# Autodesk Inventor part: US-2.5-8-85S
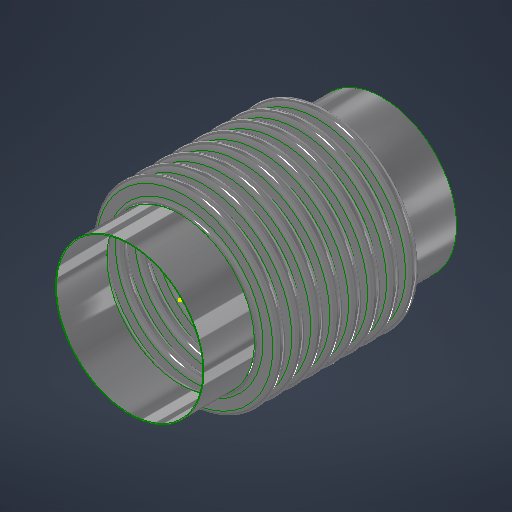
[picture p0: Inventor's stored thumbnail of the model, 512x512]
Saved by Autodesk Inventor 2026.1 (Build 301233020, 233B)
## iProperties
Category: 26 GA (0.018 THICK)
RuleStatus: InUse
Created: 2026-07
Part Number: US-2.5-8-85S
Project: =STOCK BELLOWS: <Stock Number><SFILL>
Material: ASTM A240-304
Description: =STOCK BELLOWS: <Stock Number>, <SID_> I.D., <SOD_> O.D., <SPLY_> PLY, <Category>, <SNET_CONS> CONS.<PITCH_><STANGENT_> TANGENT<SFILL>
Document SubType Name: Sheet Metal
Designer: LC
Stock Number: U.S-2.5-8-85S
Surface Area: 659.127 cm^2
Volume: 56.61 cm^3
Sheet Metal Rule: Default
Appearance: STAINLESS STEEL
NET_TUBE: 3.428
COUNTER: 1.500
PBAR: 1.214
PSET: 5.356
PLY: 2
CONS: 2
THK: 0.036
ID: 4.500
OD: 5.500
CONS_: 2
TANGENT: 0.500
PITCH: 0.375
BELLOWS_UPSET: 0.000
NET_CONS: 2
S_CONS: 0
Description_Units: 0
ID_M: 114.30 mm
OD_M: 139.70 mm
THK_M: 0.91 mm
ID_U: 4.500 in
OD_U: 5.500 in
THK_U: 0.036 in
TANGENT2: 0.500
d79: 1.000
d82: 1.000
d83: 26.000
d84: 24.000
d80: 2.571
d81: 10
SID: 2.375
SCONS_: 8
SPITCH: 0.250
SBELLOWS_UPSET: 0.000
SNET_CONS: 8
SS_CONS: 0
SCONS: 8
d174: 8
d177: 0.018
d178: 2.375
d179: 3.000
d180: 0.375
d181: 1.000
d182: 0.000
d190: 8
d191: 1
d192: 1
d193: 8
d194: 0
PART_NUMBER: U.S-2.5-8-85S
PRESSURE: 85
SIZE: 2.50
STANGENT_: 1.000
d214: 8
d217: 0.030
d218: 6.625
d219: 8.125
d220: 0.500
d221: 1.000
d222: 0.000
d230: 8
d231: 1
d232: 1
d233: 8
d234: 0
STANGENT: 4.000
SPLY_: 1
STHK_: 0.018
SID_: 2.900
SOD_: 3.700
SPITCH_: 0.375
STANGENT__: 1.000
SBELLOWS_UPSET_: 0.000
SDIFF_TAN: 1.000
TAN_TO_TAN: 0.750 in
d252: 2
d275: 2
d287: 0.050
d289: 0.500
d290: 0.000
d263: 2
d265: 1
d268: 2
d269: 0
d286: 2
d288: 1
d291: 2
d292: 0
SOD_NECK: 2 15/16
CFILL: .
SFILL: .
PITCH_: =, <SPITCH_> PITCH,
SREROLL: 0.750
MATTABLE: 20 GA (0.036 THICK)
MESH: ,
CSECT: 2
Author: LC
Keywords: 20 GA (0.036 THICK)
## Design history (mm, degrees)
sketch "Sketch2"
  geometry: L1 (0, -183.595)-(0, 600.956) reference; L2 (58.979, 0)-(57.15, 0); L3 (60.446, -1.467)-(66.554, -1.467); L4 (60.446, -3.296)-(66.554, -3.296); L5 (66.554, -8.058)-(60.446, -8.058); L6 (66.554, -6.229)-(60.446, -6.229); L7 (58.979, -9.525)-(57.15, -9.525); L8 (60.446, 0)-(60.446, -9.525); L9 (66.554, -4.762)-(69.85, -4.763); L10 (57.15, 0)-(57.15, -9.525); L11 (20.376, 102.841)-(20.376, 101.926); L12 (58.262, 488.877)-(58.262, 349.177); L13 (58.262, 479.352)-(58.262, 339.652); L14 (93.133, -58.817)-(93.133, -71.517); L15 (118.746, -66.401)-(118.746, -66.401); L16 (66.554, -6.229)-(66.554, -8.058); L17 (60.446, -6.229)-(60.446, -8.058); L18 (60.446, -7.144)-(66.554, -7.144); L19 (69.85, 0)-(69.85, -9.525); L20 (-66.554, -6.229)-(-66.554, -8.058); L21 (-66.554, -1.467)-(-60.446, -1.467); L22 (-66.554, -3.296)-(-60.446, -3.296); L23 (-60.446, -6.229)-(-66.554, -6.229); L24 (-66.554, -7.144)-(-60.446, -7.144); L25 (-60.446, -8.058)-(-66.554, -8.058); L26 (-60.446, -6.229)-(-60.446, -8.058); L27 (-57.15, -2.522)-(-57.15, -12.047); L28 (-60.446, -4.763)-(-57.15, -4.763); L29 (-66.554, 3.828)-(-66.554, -9.525); L30 (-68.021, 0)-(-69.85, 0); L31 (-69.85, 0)-(-69.85, -9.525); L32 (-68.021, -9.525)-(-69.85, -9.525); A1 r 1.467 centre (60.446, 0) between (58.979, 0) and (60.446, -1.467); A2 r 3.296 centre (60.446, 0) between (57.15, 0) and (60.446, -3.296); A3 r 3.296 centre (66.554, -4.762) between (66.554, -8.058) and (66.554, -1.467); A4 r 1.467 centre (66.554, -4.762) between (66.554, -6.229) and (66.554, -3.296); A5 r 1.467 centre (60.446, -9.525) between (60.446, -8.058) and (58.979, -9.525); A6 r 3.296 centre (60.446, -9.525) between (60.446, -6.229) and (57.15, -9.525); A7 r 2.381 centre (66.554, -4.762) between (66.554, -7.144) and (68.936, -4.762); A8 r 2.381 centre (60.446, -9.525) between (60.446, -7.144) and (58.064, -9.525); A9 r 1.467 centre (-66.554, -9.525) between (-66.554, -8.058) and (-68.021, -9.525); A10 r 1.467 centre (-60.446, -4.763) between (-60.446, -6.229) and (-60.446, -3.296); A11 r 2.381 centre (-60.446, -4.763) between (-60.446, -7.144) and (-58.064, -4.763); A12 r 3.296 centre (-60.446, -4.763) between (-60.446, -8.058) and (-60.446, -1.467); A13 r 2.381 centre (-66.554, -9.525) between (-66.554, -7.144) and (-68.936, -9.525); A14 r 3.296 centre (-66.554, -9.525) between (-66.554, -6.229) and (-69.85, -9.525); A15 r 1.467 centre (-66.554, 0) between (-68.021, 0) and (-66.554, -1.467); A16 r 3.296 centre (-66.554, 0) between (-69.85, 0) and (-66.554, -3.296); 10 further points
  constraints: 62 end point, 38 point on circle, 20 tangent, 16 centre point, 12 parallel, 9 midpoint, 7 vertical, 6 coincident, 6 concentric, 6 point on line, 4 equal radius, 4 perpendicular, 3 horizontal, 1 collinear, 1 horizontal alignment, 10 other
  dimensions: "THK" = 0.9144 distance of L11.start L11.end; "ID" = 114.3 distance of L11.end point (20.376, -12.374); "OD" = 139.7 distance of L12.start L12.end; "PITCH" = 9.525 distance of L12.start L13.start; "TANGENT" = 12.7 distance of L14.start L14.end; "BELLOWS_UPSET" = 0 distance of L15.start L15.end; "d43" = 114.3 diameter of L10 L1 (= ID); "d44" = 139.7 diameter of L9.end L1 (= OD); "d45" = 1.8288 distance between parallel lines of L5 L6 (computed from THK, PLY); "d46" = 3.29565 radius of A3 (computed from PITCH, THK, PLY); "UPSET_PITCH" = 9.525 distance of L2.end L7.end (derived); "SIDEWALL_ANGLE" = 0 deg angle of L3 L9 (derived); "CON_GAP" = 2.9337 distance of point (60.446, -6.229) point (60.446, -3.296) (derived); "TAN1" = 3.74046 dimension on A8 (derived); "TAN2" = 3.74046 dimension on A7 (derived); "LEG1" = 6.1087 distance of L18.start L18.end (derived); "d278" = 1.8288 distance between parallel lines of L25 L23 (derived); "d279" = 3.29565 radius of A12 (derived); "d280" = 9.525 distance of L30.end L31.end (derived); "d281" = 360 deg dimension on L21 L28 (derived); "d282" = 2.9337 distance of point (-66.554, -6.229) point (-66.554, -3.296) (derived); "d283" = 3.74046 dimension on A13 (derived); "d284" = 3.74046 dimension on A11 (derived); "d285" = 6.1087 distance of L24.start L24.end (derived); "d293" = 114.3 diameter of L27 L1 (derived); "d294" = 139.7 diameter of L31 L1 (derived)
  node "Sketch Rectangular Pattern1" dims "d31" = 25.4, "ID" = 114.3
  node "Sketch Rectangular Pattern2" dims "d39" = 25.4, "PITCH" = 9.525
revolve "CONS" stored, may be unused: angle "d48" = 90 deg
node "BELLOW MIDPLANE"
pattern_linear "Rectangular Pattern2" dims "d52" = 9.525 (= UPSET_PITCH)
sketch "Sketch5"
  geometry: C1 r 58.979 at (0, 0) reference; C2 r 57.15 at (0, 0) reference
extrude "TANGENT" new body sketch "Sketch5" distance "d53" = 12.7 (= TANGENT); taper "d54" = 0 deg
revolve "SAMETAN" stored, may be unused: angle "d65" = 90 deg
revolve "DIFFTAN" stored, may be unused: angle "d70" = 90 deg
sketch "Sketch9"
  geometry: L1 (58.391, 0)-(-58.391, 0) reference; L2 (0, -17.78)-(0, 17.78) reference; L3 (41.708, 0)-(-41.708, 0); L4 (41.708, -11.906)-(41.708, 11.906); L5 (29.008, -11.906)-(29.008, 11.906); L6 (15.418, 11.906)-(15.418, -11.906); L7 (-29.008, -11.906)-(-29.008, 11.906); L8 (-41.708, -11.906)-(-41.708, 11.906); L9 (40.914, -11.906)-(40.914, 11.906); L10 (41.708, -11.906)-(40.914, -11.906); L11 (41.708, 11.906)-(40.914, 11.906); L12 (15.815, 11.906)-(15.022, 11.906); L13 (15.022, 11.906)-(15.022, -11.906); L14 (15.022, -11.906)-(15.815, -11.906); L15 (15.815, -11.906)-(15.815, 11.906); L16 (-15.815, 11.906)-(-15.815, -11.906); L17 (-15.418, 11.906)-(-15.418, -11.906); L18 (-15.815, -11.906)-(-15.022, -11.906); L19 (-15.022, -11.906)-(-15.022, 11.906); L20 (-15.022, 11.906)-(-15.815, 11.906); L21 (-41.708, -11.906)-(-40.914, -11.906); L22 (-40.914, -11.906)-(-40.914, 11.906); L23 (-40.914, 11.906)-(-41.708, 11.906); L24 (-41.708, 11.906)-(-41.708, -11.906); L25 (41.708, -0.397)-(-41.708, -0.397); L26 (-41.708, -0.397)-(-41.708, 0.397); L27 (-41.708, 0.397)-(41.708, 0.397); L28 (41.708, 0.397)-(41.708, -0.397); L29 (-41.708, 11.906)-(41.708, 11.906); L30 (41.708, 11.906)-(41.708, 12.7); L31 (41.708, 12.7)-(-41.708, 12.7); L32 (-41.708, 12.7)-(-41.708, 11.906); L33 (41.708, -11.906)-(-41.708, -11.906); L34 (-41.708, -11.906)-(-41.708, -12.7); L35 (-41.708, -12.7)-(41.708, -12.7); L36 (41.708, -12.7)-(41.708, -11.906); 30 further points
  constraints: 68 end point, 13 midpoint, 13 parallel, 8 horizontal, 7 perpendicular, 6 equal length, 3 point on line, 2 vertical, 14 other
  dimensions: "d115" = 23.8125 distance of L4.start L4.end (derived); "d116" = 12.7 distance between parallel lines of L4 L5 (derived); "d117" = 13.58962 distance between parallel lines of L5 L6 (derived); "d125" = 44.42645 distance between parallel lines of L7 L6 (derived); "d127" = 12.7 distance between parallel lines of L8 L7 (derived); "d128" = 26.28962 distance between parallel lines of L6 L4 (derived); "d130" = 83.41607 distance between parallel lines of L8 L4 (derived); "RULER_THK" = 0.79375 distance between parallel lines of L4 L9; "d135" = 0.79375 distance of L13.end L14.end (derived); "d138" = 30.83684 distance of L13.end L16.end (derived); "d143" = 0.79375 distance of L22.end L8.end (derived); "d144" = 0.79375 distance between parallel lines of L27 L25 (derived)
extrude "RULER" join sketch "Sketch9" distance "d149" = 0.79375 (derived); taper "d150" = 0 deg
extrude "BARS" join sketch "Sketch9" distance "d151" = 0.79375 (derived); taper "d152" = 0 deg
pattern_linear "Rectangular Pattern4" dims "d155" = 30.83684 (derived)
sketch "Sketch13"
  geometry: L1 (93.149, -52.467)-(93.149, -77.867); L2 (37.287, 0)-(36.83, 0); L3 (37.287, -9.525)-(36.83, -9.525); L4 (44.38, -7.372)-(39.44, -7.372); L5 (44.38, -6.915)-(39.44, -6.915); L6 (44.38, -4.762)-(46.99, -4.762); L7 (39.44, -2.153)-(44.38, -2.153); L8 (39.44, 0)-(39.44, -9.525); L9 (36.83, 0)-(36.83, -9.525); L10 (58.254, -367.738)-(58.254, -461.718); L11 (58.254, -377.263)-(58.254, -471.243); L12 (58.254, -396.313)-(58.254, -490.293); L13 (58.254, -405.838)-(58.254, -499.818); L14 (58.254, -415.363)-(58.254, -509.343); L15 (58.254, -424.888)-(58.254, -518.868); L16 (58.254, -434.413)-(58.254, -528.393); L17 (58.254, -386.788)-(58.254, -480.768); L18 (20.376, 102.383)-(20.376, 101.926); L19 (39.44, -2.61)-(44.38, -2.61); L20 (0, -640.324)-(0, 226.168) reference; L21 (-23.752, 0)-(142.514, 0) reference; A1 r 2.153 centre (39.44, 0) between (37.287, 0) and (39.44, -2.153); A2 r 2.153 centre (39.44, -9.525) between (39.44, -7.372) and (37.287, -9.525); A3 r 2.61 centre (39.44, -9.525) between (39.44, -6.915) and (36.83, -9.525); A4 r 2.153 centre (44.38, -4.762) between (44.38, -6.915) and (44.38, -2.61); A5 r 2.61 centre (44.38, -4.762) between (44.38, -7.372) and (44.38, -2.153); A6 r 2.61 centre (39.44, 0) between (36.83, 0) and (39.44, -2.61); 6 further points; 1 other entity
  constraints: 38 end point, 15 point on circle, 9 tangent, 6 centre point, 6 parallel, 5 vertical alignment, 4 point on line, 4 vertical, 3 coincident, 3 concentric, 2 collinear, 2 equal radius, 1 horizontal, 1 perpendicular, 23 other
  dimensions: "SBELLOWS_UPSET_" = 0 distance of point (118.762, -66.401) point (118.762, -66.401); "STOTAL_THK_BELLOW__" = 0.4572 distance between parallel lines of L4 L5 (derived); "d224" = 2.60985 radius of A5 (derived); "d225" = 9.525 distance of L2.end L3.end (derived); "SSIDEWALL_ANGLE_" = 0 deg angle of L7 L6 (derived); "SSCON_GAP_" = 4.3053 distance of point (39.44, -6.915) point (39.44, -2.61) (derived); "d235" = 73.66 diameter of L9 L20 (derived); "d236" = 93.98 diameter of L6.end L20 (derived)
  node "Sketch Rectangular Pattern4" dims "d228" = 25.4
  node "Sketch Rectangular Pattern5" dims "d229" = 25.4
revolve "SBELLOW" stored, may be unused: angle "d197" = 90 deg
pattern_linear "Rectangular Pattern5" dims "d204" = 9.525 (derived)
revolve "STANGENT" stored, may be unused: angle "d240" = 90 deg
revolve "SSAMETAN" stored, may be unused: angle "d241" = 90 deg
revolve "SDIFFTAN" stored, may be unused: angle "d246" = 90 deg
revolve "INVCON" stored, may be unused: angle "d295" = 90 deg
pattern_linear "Rectangular Pattern6" dims "d298" = 9.525 (derived)
revolve "INVTANGENT" stored, may be unused: angle "d302" = 90 deg
revolve "INVSAMETAN" stored, may be unused: angle "d307" = 90 deg
revolve "INVDIFFTAN" stored, may be unused: angle "d312" = 90 deg
sketch "ID BELLOW MOUNT CALC"
  geometry: L1 (44.45, 0)-(38.1, 0); L2 (38.1, 0)-(38.1, 12.7); L3 (38.1, 12.7)-(44.45, 12.7); L4 (44.45, 12.7)-(44.45, 0); L5 (36.513, 12.7)-(34.684, 12.7); L6 (34.684, 12.7)-(34.684, 0); L7 (34.684, 0)-(36.513, 0); L8 (36.513, 0)-(36.513, 12.7); L9 (0, -2.54)-(0, 15.24) reference; L10 (-8.89, 0)-(53.34, 0) reference; 1 further point
  constraints: 16 end point, 5 parallel, 2 collinear, 2 horizontal, 2 perpendicular
  dimensions: "d314" = 12.7 distance of L5.end L6.end (derived); "d315" = 1.8288 distance of L5.start L5.end (derived); "IG" = 1.5875 distance between parallel lines of L2 L8; "PIPE_OD" = 88.9 diameter of L4 L9; "PIPE_WALL" = 6.35 distance of L2.end L3.end; "ID_MT_BELLOW" = 69.3674 diameter of L6 L9 (derived)
revolve "CFILL" stored, may be unused: angle "d320" = 90 deg
pattern_linear "Rectangular Pattern7" dims "d323" = 9.525 (derived)
revolve "SFILL" stored, may be unused: angle "d324" = 90 deg
pattern_linear "Rectangular Pattern8" dims "d327" = 9.525 (derived)
node "STOCK BELLOW MIDPLANE"
sketch "Sketch21"
  geometry: L1 (0, -100.013)-(0, 100.013) reference; L2 (-100.013, 0)-(100.013, 0) reference; L3 (-0.099, 71.437)-(0.099, 71.437); L4 (0.099, 71.437)-(0.099, 55.562); L5 (0.099, 55.562)-(-0.099, 55.562); L6 (-0.099, 55.562)-(-0.099, 71.437); C1 r 55.562 at (0, 0); C2 r 71.437 at (0, 0); 3 further points
  constraints: 8 end point, 2 centre point, 2 coincident, 2 parallel, 2 tangent, 1 horizontal, 1 perpendicular, 1 other
  dimensions: "d329" = 111.125 diameter of C1 (derived); "d330" = 142.875 diameter of C2 (derived); "d331" = 0.19844 distance of L3.start L3.end
extrude "CLAMSHELL" cut sketch "Sketch21" extent not by distance; stored distance "d332" = 0; taper "d333" = 0 deg
pattern_circular "Circular Pattern1" dims angle "d335" = 180 deg (derived)
node "BELLOW"
sketch "Sketch6"
  geometry: L1 (-19.05, 58.979)-(-6.35, 58.979); L2 (-6.35, 58.979)-(-6.35, 57.15); L3 (-6.35, 57.15)-(-19.05, 57.15); L4 (-19.05, 57.15)-(-19.05, 58.979); L5 (2.54, 0)-(-59.69, 0) reference; L6 (-38.1, -108.388)-(-38.1, 156.601) reference; 1 further point
  constraints: 8 end point, 2 parallel, 1 horizontal, 1 perpendicular
  dimensions: "d61" = 12.7 distance of L2.end L3.end (derived); "d62" = 1.8288 distance of L1.end L2.end (derived); "d63" = 114.3 diameter of L3 L5 (derived); "d64" = 19.05 distance between parallel lines of L4 L6 (derived)
sketch "Sketch12"
  geometry: 1 further point
sketch "Sketch14"
  geometry: L1 (-25.4, 37.287)-(0, 37.287); L2 (0, 37.287)-(0, 36.83); L3 (0, 36.83)-(-25.4, 36.83); L4 (-25.4, 36.83)-(-25.4, 37.287); L5 (5.08, 0)-(-30.48, 0) reference; L6 (0, -8.89)-(0, 53.34) reference; 1 further point
  constraints: 8 end point, 2 parallel, 1 collinear, 1 horizontal, 1 perpendicular
  dimensions: "d237" = 0.4572 distance of L3.end L1.start (derived); "d238" = 73.66 diameter of L3 L5 (derived); "d239" = 25.4 distance of L1.start L1.end (derived); "SOD_NECK" = 74.5744 diameter of L1 L5 (derived)
sketch "Sketch15"
  geometry: L1 (-8.89, 0)-(53.34, 0) reference; L2 (36.83, -76.2)-(37.287, -76.2); L3 (37.287, -76.2)-(37.287, -101.6); L4 (37.287, -101.6)-(36.83, -101.6); L5 (36.83, -101.6)-(36.83, -76.2); L6 (0, -124.46)-(0, 35.56) reference; 1 further point
  constraints: 8 end point, 2 parallel, 1 horizontal, 1 perpendicular
  dimensions: "d205" = 25.4 distance of L4.end L2.start (derived); "d206" = 0.4572 distance of L3.end L4.end (derived); "d207" = 73.66 diameter of L5 L6 (derived); "d208" = 76.2 distance between parallel lines of L1 L2 (derived)
node "TANGENT_"
node "SAME_TAN"
sketch "Sketch8"
  geometry: L1 (58.979, -19.05)-(57.15, -19.05); L2 (57.15, -19.05)-(57.15, -31.75); L3 (57.15, -31.75)-(58.979, -31.75); L4 (58.979, -31.75)-(58.979, -19.05); L5 (0, -40.64)-(0, 21.59) reference; L6 (-108.388, 0)-(156.601, 0) reference; 1 further point
  constraints: 8 end point, 2 parallel, 1 horizontal, 1 perpendicular
  dimensions: "d66" = 114.3 diameter of L2 L5 (derived); "TOTAL_THK_BELLOW" = 1.8288 distance of L2.end L3.end (derived); "d68" = 19.05 distance between parallel lines of L1 L6 (derived); "d69" = 12.7 distance of L1.end L2.end (derived)
node "DIFF_TAN"
node "Sketch Rectangular Pattern3" dims "d138" = 30.83684 (derived), "d141" = 25.4
node "SBELLOW_"
node "STANGENT_"
node "SSAME_TAN"
sketch "Sketch16"
  geometry: L1 (37.287, -76.2)-(36.83, -76.2); L2 (36.83, -76.2)-(36.83, -101.6); L3 (36.83, -101.6)-(37.287, -101.6); L4 (37.287, -101.6)-(37.287, -76.2); L5 (0, -124.46)-(0, 35.56) reference; L6 (-8.89, 0)-(53.34, 0) reference; 1 further point
  constraints: 8 end point, 2 parallel, 1 horizontal, 1 perpendicular
  dimensions: "SDIFF_TAN" = 25.4 distance of L3.end L1.start; "d243" = 0.4572 distance of L2.end L3.end (derived); "d244" = 76.2 distance between parallel lines of L1 L6 (derived); "d245" = 73.66 diameter of L2 L5 (derived)
node "SDIFF_TAN"
body "Solid15"
sketch "Sketch17"
  geometry: L1 (69.85, 12.7)-(68.021, 12.7); L2 (68.021, 12.7)-(68.021, 0); L3 (68.021, 0)-(69.85, 0); L4 (69.85, 0)-(69.85, 12.7); L5 (0, -2.54)-(0, 15.24) reference; L6 (-13.97, 0)-(83.82, 0) reference; 2 further points
  constraints: 8 end point, 2 parallel, 1 horizontal, 1 midpoint, 1 perpendicular, 1 point on line
  dimensions: "INVTANGENT" = 12.7 distance of L3.end L1.start (derived); "d300" = 1.8288 distance of L1.start L1.end (derived); "d301" = 139.7 diameter of L4 L5 (derived)
body "Solid16"
sketch "Sketch18"
  geometry: L1 (69.85, -19.05)-(68.021, -19.05); L2 (68.021, -19.05)-(68.021, -31.75); L3 (68.021, -31.75)-(69.85, -31.75); L4 (69.85, -31.75)-(69.85, -19.05); L5 (-13.97, 0)-(83.82, 0) reference; L6 (0, -40.64)-(0, 21.59) reference; 1 further point
  constraints: 8 end point, 2 parallel, 1 horizontal, 1 perpendicular
  dimensions: "d303" = 19.05 distance between parallel lines of L1 L5 (derived); "d304" = 12.7 distance of L3.end L1.start (derived); "d305" = 1.8288 distance of L2.end L3.end (derived); "d306" = 139.7 diameter of L4 L6 (derived)
body "Solid17"
sketch "Sketch19"
  geometry: L1 (69.85, -19.05)-(68.021, -19.05); L2 (68.021, -19.05)-(68.021, -31.75); L3 (68.021, -31.75)-(69.85, -31.75); L4 (69.85, -31.75)-(69.85, -19.05); L5 (0, -40.64)-(0, 21.59) reference; L6 (-13.97, 0)-(83.82, 0) reference; 1 further point
  constraints: 8 end point, 2 parallel, 1 horizontal, 1 perpendicular
  dimensions: "d308" = 12.7 distance of L1.end L2.end (derived); "d309" = 139.7 diameter of L4 L5 (derived); "d310" = 1.8288 distance of L2.end L3.end (derived); "d311" = 19.05 distance between parallel lines of L1 L6 (derived)
body "Solid18"
body "Solid19"
body "Solid20"
other parameters: "BMPL" = -38.1, "PSET" = 136.0424 (computed from OD, THK, PLY) [user parameter], "PBAR" = 30.83684 (= 0.570796 x PITCH + OD - ID) [user parameter; used in 1 equation term], "COUNTER" = 15 [user parameter], "NET_TUBE" = 87.07367 (computed from CONS_, PBAR, TANGENT) [user parameter], "S_CONS" = 0 [user parameter; used in 1 equation term], "ID_M" = 114.3 (= ID) [user parameter], "OD_M" = 139.7 (= OD) [user parameter], "THK_M" = 0.9144 (= THK) [user parameter], "ID_U" = 114.3 (= ID) [user parameter], "OD_U" = 139.7 (= OD) [user parameter], "THK_U" = 0.9144 (= THK) [user parameter], "D_UNITS" = 0 [user parameter], "TANGENT2" = 12.7 [user parameter], "TAN_TO_TAN" = 19.05 [user parameter], "OD_NECK" = 117.9576 [user parameter], "d79" = 25.4, "d80" = 65.29823 [user parameter], "d82" = 25.4, "d83" = 660.4, "d84" = 609.6, "sa_0" = 4, "FRAME_THK" = 0.79375 [user parameter], "CON_FLAT" = 13.58962 [user parameter], "SID" = 60.325 [user parameter], "SPITCH" = 6.35 [user parameter], "STANGENT_" = 25.4 [user parameter], "SBELLOWS_UPSET" = 0 [user parameter], "SS_CONS" = 0 [user parameter], "STAN_TO_TAN_" = 76.2 [user parameter], "d100" = 0.4572 [user parameter], "d191" = 25.4 [user parameter], "d194" = 0 [user parameter], "STANGENT" = 101.6 [user parameter], "d234" = 0 [user parameter], "SUPSET_PITCH_" = 9.525 [user parameter], "d269" = 0 [user parameter], "d287" = 1.27, "d289" = 12.7, "d290" = 0, "d292" = 0 [user parameter], "Thickness" = 3.048 (derived), "KFactor" = 4.4, "BendRadius" = 3.048 (derived), "BendReliefWidth" = 3.048 (derived), "BendReliefDepth" = 1.524 (derived), "CornerReliefSize" = 12.192 (derived), "SeamGap" = 0.00508, "MinimumRemnant" = 6.096 (derived), "TransitionRadius" = 3.048 (derived), "JacobiRadiusSize" = 3.048 (derived), "GapSize" = 3.048 (derived), "SREROLL" = 19.05 [user parameter], "CUR_STK_PITCH" = 9.525 [user parameter], "d328" = -38.1 (derived), "CSECTDEG" = 180 deg [user parameter]
